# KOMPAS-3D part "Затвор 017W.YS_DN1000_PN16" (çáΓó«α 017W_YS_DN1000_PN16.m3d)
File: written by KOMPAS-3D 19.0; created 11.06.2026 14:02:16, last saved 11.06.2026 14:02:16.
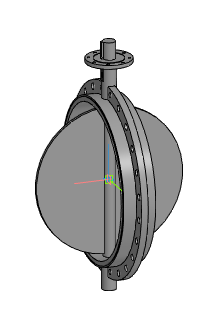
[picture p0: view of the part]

Document properties: Автор: Евгений; Полное имя файла: Z:\3.Личные\kachalov\001_3d для проектировщиков\x.x Тип 017W.Y(S) Затвор дисковый поворотный межфланцевый\_stp_Затвор 017W.YS_DN32-DN1200\Затвор 017W_YS_DN1000_PN16.m3d

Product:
- Part/product: Затвор 017W.YS_DN1000_PN16

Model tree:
1. Операция без истории:1  (labels: Затвор 017W.YS_DN1000_PN16)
